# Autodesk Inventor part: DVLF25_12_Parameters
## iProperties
Created: 2010-03
Part Number: DVLF25_12_Parameters
Document SubType Name: Modeling
Designer: TB
Density: 1 g/cm^3
Slaglengde: 100.000 mm
Vinkel_Plussport: 0.00 deg
Vinkel_Minusport: 0.00 deg
Forlengelse_rør: 0.000 mm
Author: TB
